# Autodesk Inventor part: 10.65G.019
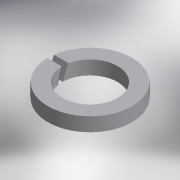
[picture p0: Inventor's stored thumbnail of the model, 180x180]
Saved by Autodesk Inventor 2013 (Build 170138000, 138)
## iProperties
Shininess: 25.0
Length Units: 11269
Angle Units: 11279
Time Units: 11290
Mass Units: 11283
Length Display Precision: 3
Angle Display Precision: 2
Created: 2001-04
Material: Steel, Mild
Description: Шайба 10.65Г.019 ГОСТ 6402-70
Document SubType Name: Modeling
Designer: tevgeniy
Mass: 1.96655 g
Surface Area: 4.06504 cm^2
Volume: 0.250197 cm^3
Density: 7.86 g/cm^3
Density: 7.86
Volumn: 0.2501956736428592
Area: 4.065041569612211
PropertySet Name: Model Information
Control State: 0
Master: False
Checked Out: False
Last Check In Date: 2008-10-15
Checked Out Date: 2008-10-15
Author: tevgeniy
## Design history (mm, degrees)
node "ExtrusionBlind1" dims "d2" = 2.5, "d3" = 0
  sketch "Sketch1"
    geometry: C1 r 7.6 at (-266.435, -313.047)
    constraints: 1 centre point, 1 other
    dimensions: "d1" = 15.2 diameter of C1
node "Hole1" dims "d5" = 10, "d6" = 4, "d7" = 2, "d8" = 60 deg, "d9" = 8, "d10" = 118 deg
  sketch "Sketch2"
    geometry: C1 r 7.6 at (0, 0) reference
node "WorkPlane1"
node "ExtrusionToFace1" dims "d18" = 0.13, "d19" = 0
  sketch "Sketch3"
    geometry: L1 (-21.641, 0.09)-(-21.641, -1); L2 (-19.141, 1)-(-21.641, 0.09); L3 (-19.141, -0.09)-(-19.141, 1); L4 (-21.641, -1)-(-19.141, -0.09); L5 (-9.571, 0)-(-31.211, 0); C1 r 7.6 at (-19.141, 0); C2 r 7.6 at (-21.641, 0)
    constraints: 10 end point, 2 centre point, 2 parallel, 1 vertical
    dimensions: "d13" = 0 horizontal distance of L2.start C1.centre; "d15" = 0 horizontal distance of L1.start C2.centre; "d17" = 160 deg angle of L4 L5
body "Solid1"
other parameters: "d0" = 15.2 (derived), "d4" = 0, "d12" = 0 (derived), "d14" = 0 (derived), "d16" = 160 deg (derived), "d20" = 0
